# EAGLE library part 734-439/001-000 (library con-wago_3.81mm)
Serie 734, Doppelstock-Stiftleisten Einlötstift abgewinkelt 1 x 1 mm / Series 734, Double-deck male headers Angled solder pin 1 x 1 mm Polzahl / Pole No.: 9 Rastermaß / Pitch: 3.81 mm Bemessungsspannung / Rated Voltage: 160 V Nennstrom / Nominal Current: 10 A Lötstiftlänge: / Solder Pin Length: 3.6 mm Farbe / Color: orange / orange Stand: 01.01.2012. Die jeweils aktuellen Daten zu diesem Artikel finden Sie in unserem Produktkatalog, den Sie unter www.wago.com einsehen können. As of: 01/01/2012. Please find the newest data for this article in our product catalogue, which can be viewed under www.wago.com.
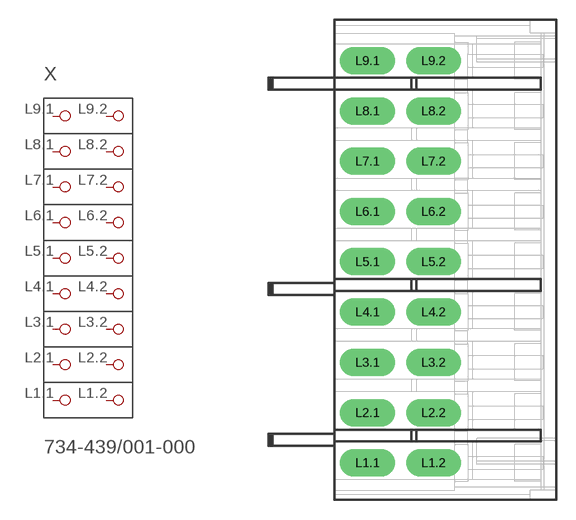
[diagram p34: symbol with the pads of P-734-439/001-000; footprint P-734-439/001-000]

Designator prefix X

## 734-439/001-000  [P-734-439/001-000]
L1.1  P1.1
L1.2  P1.2
L2.1  P2.1
L2.2  P2.2
L3.1  P3.1
L3.2  P3.2
L4.1  P4.1
L4.2  P4.2
L5.1  P5.1
L5.2  P5.2
L6.1  P6.1
L6.2  P6.2
L7.1  P7.1
L7.2  P7.2
L8.1  P8.1
L8.2  P8.2
L9.1  P9.1
L9.2  P9.2

## Footprint P-734-439/001-000 (pad centres in mm)
drill 1.4 long: L1.1 -3.4,-15.39; L1.2 1.6,-15.39; L2.1 -3.4,-11.59; L2.2 1.6,-11.59; L3.1 -3.4,-7.78; L3.2 1.6,-7.78; L4.1 -3.4,-3.96; L4.2 1.6,-3.96; L5.1 -3.4,-0.15; L5.2 1.6,-0.15; L6.1 -3.4,3.66; L6.2 1.6,3.66; L7.1 -3.4,7.47; L7.2 1.6,7.47; L8.1 -3.4,11.28; L8.2 1.6,11.28; L9.1 -3.4,15.09; L9.2 1.6,15.09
